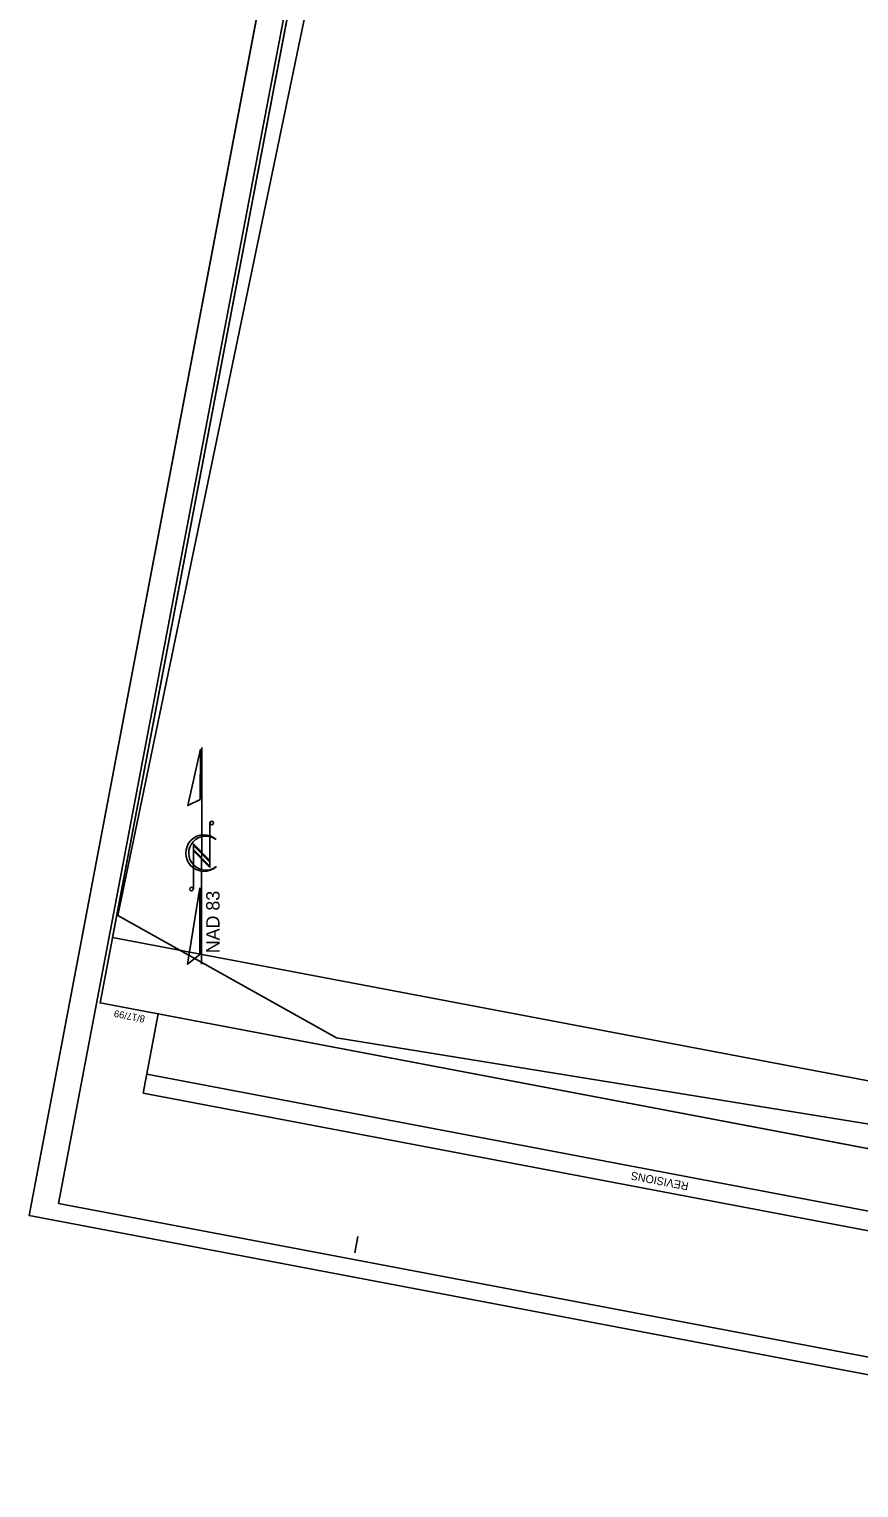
# Model space of a CAD drawing. Extents: x 1615685 to 1617075, y 899072 to 901363.
# Drawn here: x 1615685 to 1616307, y 899309 to 900402 of the extents above; entities that cross this region are included whole.
import ezdxf

# ---------------------------------------------------------------- set-up
doc = ezdxf.new("R2010")
doc.units = 0
for name, color, linetype in [('Exist Plan Preparation Drainage Flow Arrows', 7, 'Continuous'), ('Exist Plan Preparation Drainage Notes Label', 7, 'Continuous'), ('Exist Structure Minor Pipes CMP 24 Inch Text', 7, 'Continuous'), ('Exist Structure Minor Pipes RCP 12 Inch Text', 7, 'Continuous'), ('Prop Drainage Structure Catch Basin Grate 840 03E CELL', 7, 'Continuous'), ('Prop Drainage Structure Drop Inlet Grate 840 16 CELL', 7, 'Continuous'), ('Prop Drainage Structure Plot Symbol 20 Scale', 7, 'Continuous'), ('Scratch_Level_3', 7, 'Continuous'), ('Scratch_Level_8', 7, 'Continuous')]:
    doc.layers.add(name, color=color, linetype=linetype)

msp = doc.modelspace()

# ---------------------------------------------------------------- linework, layer by layer
at = {"layer": 'Exist Plan Preparation Drainage Flow Arrows'}
msp.add_lwpolyline([(1616744, 899325.3), (1617054.7, 900962.1), (1616018.3, 901158.9), (1615707.5, 899522.1)], close=True, dxfattribs=at)
at = {"layer": 'Exist Plan Preparation Drainage Notes Label'}
msp.add_lwpolyline([(1616761.2, 899308.8), (1617075.3, 900962.8), (1615999.5, 901167), (1615685.4, 899513.1)], close=True, dxfattribs=at)
at = {"layer": 'Exist Structure Minor Pipes CMP 24 Inch Text'}
for p, q in [((1615999.5, 901167), (1615685.4, 899513.1)), ((1615685.4, 899513.1), (1616761.2, 899308.8))]:
    msp.add_line(p, q, dxfattribs=at)
at = {"layer": 'Exist Structure Minor Pipes RCP 12 Inch Text'}
for p, q in [((1615814.7, 899701.4), (1615814.9, 899863.9)), ((1615820.9, 899807.3), (1615820.9, 899774)), ((1615820.9, 899779.2), (1615808.5, 899791.6)), ((1615808.5, 899791.6), (1615808.5, 899757.7)), ((1615820.9, 899778), (1615808.5, 899790.4)), ((1615808.5, 899790.4), (1615808.5, 899787.3)), ((1615820.9, 899774.9), (1615808.5, 899787.3)), ((1615808.5, 899787.3), (1615820.9, 899774.9)), ((1615820.9, 899774), (1615808.5, 899786.4)), ((1615825.5, 899794.9), (1615825.7, 899794.8)), ((1615820.9, 899774.9), (1615820.9, 899778))]:
    msp.add_line(p, q, dxfattribs=at)
for points in [[(1615813.8, 899862.5), (1615804.4, 899820.3), (1615813.7, 899825)], [(1615813.4, 899758.6), (1615804.2, 899701.4), (1615813.4, 899708.6)]]:
    msp.add_lwpolyline(points, close=True, dxfattribs=at)
for centre in [(1615822.3, 899807.3), (1615807.1, 899757.7)]:
    msp.add_circle(centre, 1.33, dxfattribs=at)
for centre, radius, start, end in [((1615816.5, 899784.7), 13.7, 47.7813, 312.3353), ((1615817.8, 899784.7), 12.8, 53.0363, 308.5699)]:
    msp.add_arc(centre, radius, start, end, dxfattribs=at)
at = {"layer": 'Prop Drainage Structure Catch Basin Grate 840 03E CELL'}
msp.add_lwpolyline([(1616779.5, 899525.7), (1617040.6, 900901.1), (1616216.8, 901057.5), (1616181.5, 900871.6), (1615973.8, 900911), (1615747.9, 899721.5)], close=True, dxfattribs=at)
at = {"layer": 'Prop Drainage Structure Drop Inlet Grate 840 16 CELL'}
msp.add_lwpolyline([(1615738.6, 899672.4), (1616770.2, 899476.6), (1617050, 900950.2), (1616226.2, 901106.6), (1616181.5, 900871.6), (1615973.8, 900911)], close=True, dxfattribs=at)
at = {"layer": 'Prop Drainage Structure Plot Symbol 20 Scale'}
msp.add_lwpolyline([(1616187.5, 901058.3), (1617033, 900874.1), (1617012.2, 900781.1), (1616950.6, 900773.3), (1616752.7, 900760.6), (1616722.4, 900593.6), (1616951.1, 900496.7), (1616753.2, 899510.4), (1615915.8, 899646.2), (1615751.8, 899738), (1615999.4, 900929.1), (1616157.9, 900902)], close=True, dxfattribs=at)
at = {"layer": 'Scratch_Level_3'}
msp.add_line((1616550.4, 899471.5), (1615773.6, 899619), dxfattribs=at)
msp.add_lwpolyline([(1616547.7, 899457.2), (1615770.9, 899604.7), (1615782.2, 899664.2), (1616558.9, 899516.7)], close=True, dxfattribs=at)
at = {"layer": 'Scratch_Level_8'}
for p, q in [((1615738.6, 899672.4), (1615738.6, 899672.4)), ((1615929.5, 899485), (1615931.8, 899497.3))]:
    msp.add_line(p, q, dxfattribs=at)
for points in [[(1616018.4, 901146.1), (1615738.6, 899672.4), (1616770.2, 899476.6), (1617050, 900950.2)], [(1616770.2, 899476.6), (1615738.6, 899672.4), (1615981.1, 900949.6), (1616128.5, 900921.6), (1616165.8, 901118.1), (1617050, 900950.2)]]:
    msp.add_lwpolyline(points, close=True, dxfattribs=at)

# ---------------------------------------------------------------- texts
at = {"layer": 'Exist Structure Minor Pipes RCP 12 Inch Text'}
msp.add_text('NAD 83', height=10, rotation=89.9412, dxfattribs=at).set_placement((1615828.1, 899709.6))
at = {"layer": 'Scratch_Level_3'}
msp.add_text('REVISIONS', height=6, rotation=169.2494, dxfattribs=at).set_placement((1616180.1, 899537.7))
at = {"layer": 'Scratch_Level_8'}
msp.add_text('8/17/99', height=5.25, rotation=169.2494, dxfattribs=at).set_placement((1615772.6, 899662.7))

doc.saveas('drawing.dxf')
